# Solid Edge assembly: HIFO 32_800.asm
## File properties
Title: Zylinder
Author: ahadarics
Template: iso assembly.asm
Last saved by: ahadarics
Revision: 78
Application: Solid Edge
Username: ahadarics
Dokumentum tartalom típus: 1
Document Number: HIFO 32/800
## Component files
Profilrohr 32_800.par
Kit_1.par
Mutter.par
Kit_2.par
Kolbenstange 32_800.par
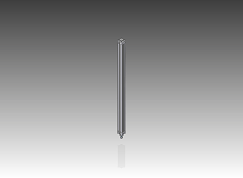
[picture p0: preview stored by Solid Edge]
